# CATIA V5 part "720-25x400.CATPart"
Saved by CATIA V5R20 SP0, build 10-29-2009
Part number: 720-25x400
Definition: NONE
Nomenclature: 720-25x400
Source: Unknown
Description: 720-25x400
Bounding box of the stored display mesh (mm): x 0 to 400, y -12.5 to 12.5, z -12.5 to 12.5
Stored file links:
  C:\Users\Utente\Desktop\IO LAVORO\3D X SITO CF\X SITO\720\720-25x400.CATPart
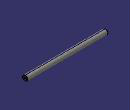
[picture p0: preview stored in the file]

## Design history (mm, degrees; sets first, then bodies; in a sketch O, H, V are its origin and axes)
Body1 "720-25x400" (main body)
  Solid1: solid without history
